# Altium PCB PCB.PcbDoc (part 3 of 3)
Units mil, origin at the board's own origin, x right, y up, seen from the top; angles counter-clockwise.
Board outline 5000 x 3500 mil, 8 copper layers (Top Layer, L2, L3, L4, L5, L6, L7, Bottom Layer), stack 46.9 mil thick; 123 components, 45 nets, 510 pads, 1300 vias.
Unrouted connection lines stored in the file: 12.
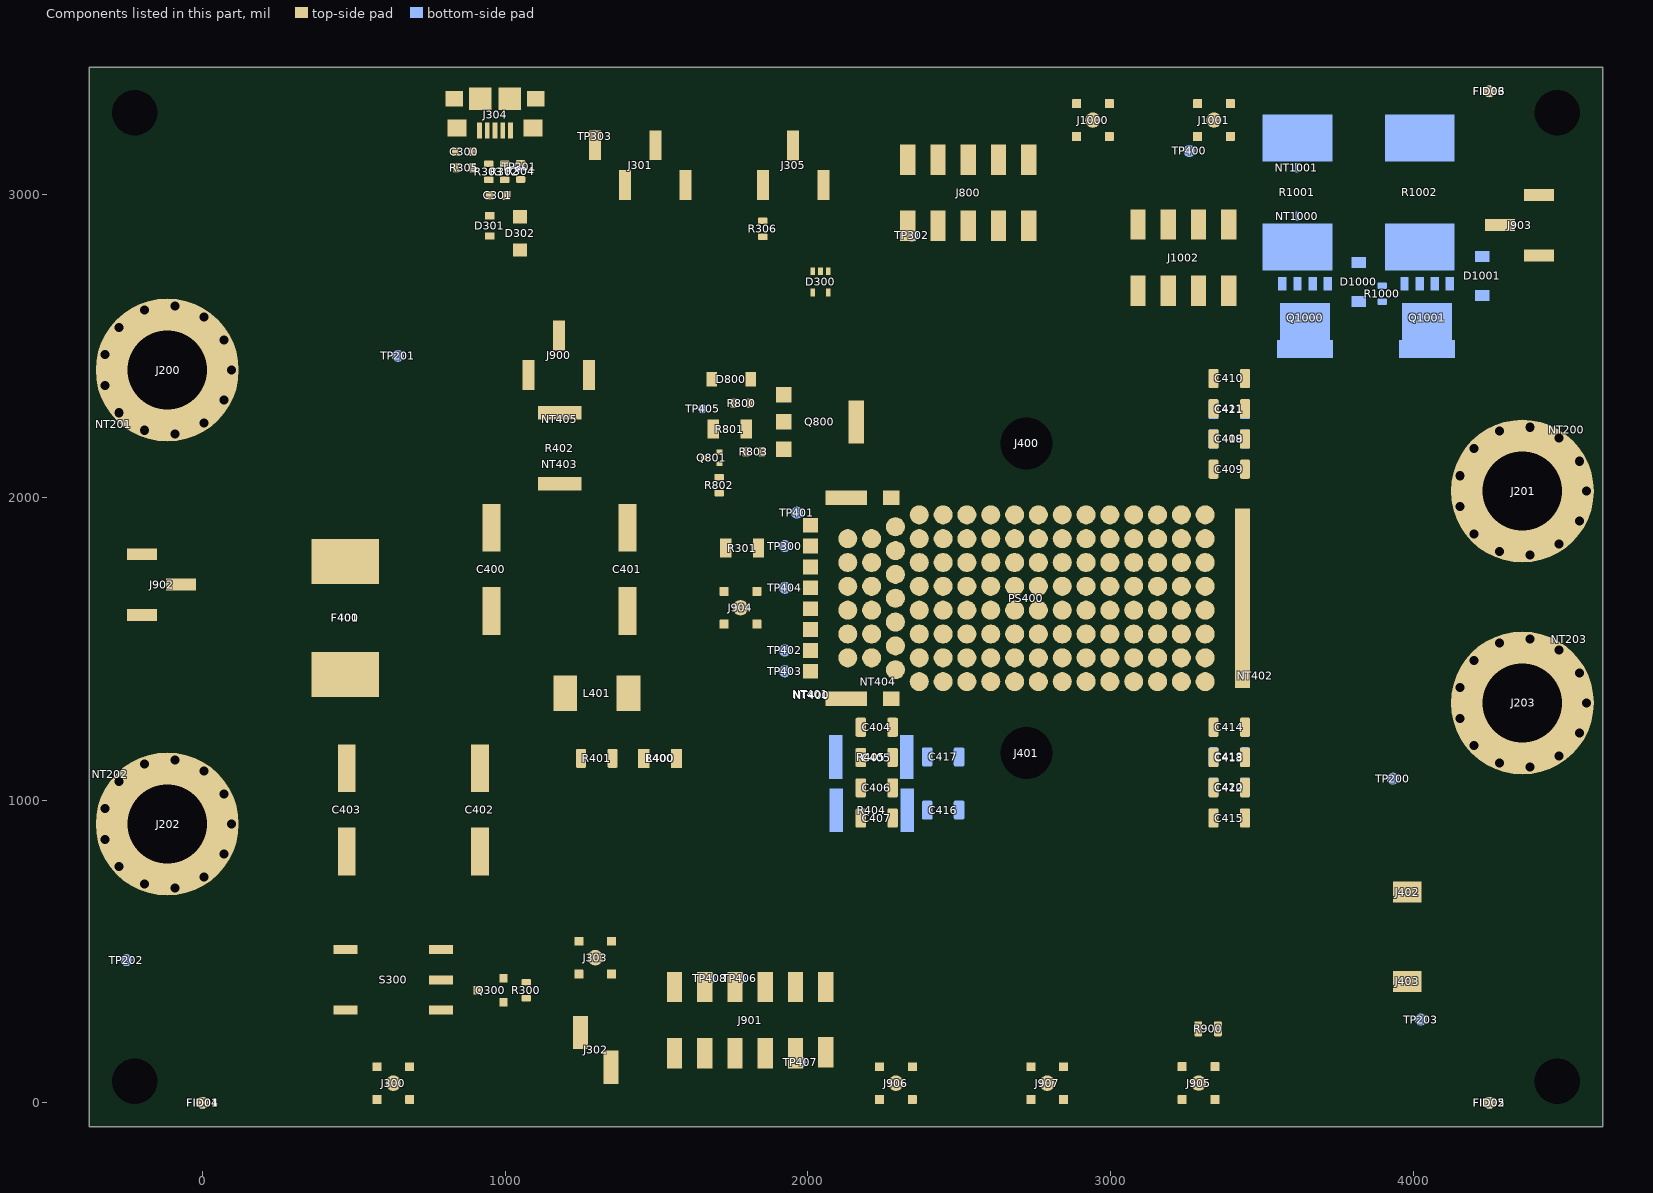
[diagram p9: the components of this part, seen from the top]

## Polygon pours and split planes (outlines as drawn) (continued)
QDISG on Top Layer "Top-No Net" (solid, remove dead copper, pour order 16200): 2492.46,3196 2492.46,3064.42 2668.46,3064.42 2668.46,3196
RDISG on Top Layer "Top-No Net" (solid, remove dead copper, pour order 16177): 2592.46,2950.09 2668.46,2950.09 2668.46,2810.09 2592.46,2810.09
SCL on Top Layer "Top-No Net" (solid, remove dead copper, pour order 16190): 1264.69,3112.32 1328.69,3112.32 1365.71,3149.35 1365.71,3252.32 1226.34,3252.32 1226.34,3150.67
SDA on Top Layer "Top-No Net" (solid, remove dead copper, pour order 16192): 1430.03,3086.36 1363.35,3086.36 1326.5,3049.51 1326.5,2946.36 1465.87,2946.36 1465.87,3050.51
VSS on Top Layer "Top-No Net" (solid, remove dead copper, pour order 16191): 1629.87,3086.51 1563.51,3086.51 1526.34,3049.35 1526.34,2946.51 1665.71,2946.51 1665.71,3050.67
EN_EXT on Top Layer "Top-No Net" (solid, remove dead copper, pour order 16189): 1464.69,3112.32 1528.69,3112.32 1565.71,3149.35 1565.71,3252.32 1426.34,3252.32 1426.34,3150.67
VDDB_EXT on Top Layer "Top-No Net" (solid, remove dead copper, pour order 16188): 1880.12,3085.21 1821.53,3085.21 1781.6,3045.27 1781.6,2945.21 1920.97,2945.21 1920.97,3044.36
VSS on Top Layer "Top-No Net" (solid, remove dead copper, pour order 16185): 2079.96,3085.37 2021.69,3085.37 1981.44,3045.12 1981.44,2945.37 2120.81,2945.37 2120.81,3044.52
VSS on Top Layer "Top-No Net" (solid, remove dead copper, pour order 16194): 1915.38,3111.18 1986.87,3111.18 2020.81,3145.12 2020.81,3251.18 1881.44,3251.18 1881.44,3145.12
RESR_HI on Top Layer "Top-No Net" (solid, remove dead copper, pour order 16180): 1106,2457.3 1047.41,2457.3 1007.47,2417.36 1007.47,2325.89 1146.84,2325.89 1146.84,2416.45
RESR_LO on Top Layer "Top-No Net" (solid, remove dead copper, pour order 16181): 1306.43,2457.46 1247.56,2457.46 1207.32,2417.21 1207.31,2325.89 1346.68,2325.89 1346.68,2417.21
VSS on Top Layer "Top-No Net" (solid, remove dead copper, pour order 16193): 1141.25,2483.27 1212.75,2483.27 1246.68,2517.21 1246.69,2623.27 1107.32,2623.27 1107.32,2517.21
S_P48V_IN on Top Layer "Top-No Net" (solid, remove dead copper, pour order 16187): -148.91,1783.6 -148.91,1842.19 -188.84,1882.13 -288.91,1882.13 -288.91,1742.76 -189.75,1742.76
S_VSS_IN on Top Layer "Top-No Net" (solid, remove dead copper, pour order 16184): -148.75,1583.76 -148.75,1642.03 -189,1682.28 -288.75,1682.28 -288.75,1542.91 -189.6,1542.91
VSS on Top Layer "Top-No Net" (solid, remove dead copper, pour order 16196): -122.94,1748.34 -122.94,1676.85 -89,1642.91 17.06,1642.91 17.06,1782.28 -89,1782.28
EN_EXT on Top Layer "Top-No Net" (solid, remove dead copper, pour order 16183): 1377.84,169.39 1324.55,169.39 1279.31,124.15 1279.31,29.39 1418.68,29.39 1418.69,128.54
EN on Top Layer "Top-No Net" (solid, remove dead copper, pour order 16199): 1220.16,180.61 1273.45,180.61 1318.69,225.85 1318.69,350 1179.32,350 1179.31,221.46
S_VSS_OUT on Top Layer "Top-No Net" (solid, remove dead copper, pour order 16182): 4364.68,2829.1 4364.68,2775.81 4409.93,2730.57 4504.68,2730.57 4504.68,2869.94 4405.53,2869.94
S_P12V2_OUT on Top Layer "Top-No Net" (solid, remove dead copper, pour order 16186): 4364.68,3029.1 4364.68,2970.82 4404.93,2930.57 4504.68,2930.57 4504.68,3069.94 4405.53,3069.94
P12V2 on Top Layer "Top Layer-P12V2" (solid, remove dead copper, pour order 16223): 3452.97,-78.74 4625.98,-78.74 4625.98,850.26 4625.98,2675.39 4260.98,2675.38 4117.57,2818.8 4117.57,3070 3459.39,3070 3459.39,2585.16 3403.1,2528.87 3403.1,2516.9 3402.48,2031.15 3403.39,2030.24 3411.89,2021.75 3411.89,1960.08 3413.63,1960.08 3414.45,1315.41 3403.39,1304.35 3403.39,242.98 3452.97,193.4
VSS on Top Layer "Top-No Net" (solid, remove dead copper, pour order 16216): 4626.74,1614 4029,1614 4029,1029 4626.74,1029
no net on Top Layer "Top-No Net" (solid, remove dead copper, pour order 16175): 4620,1610
VSS on Top Layer "Top-No Net" (solid, pour order 16215): 4200,3096 4200,3400 3217.97,3400 3217.97,3096
VSS on Top Layer "Top-No Net" (solid, pour order 16206): 3056.97,3147.52 3056.97,3347.46 2826.97,3347.46 2826.97,3147.52
VSS on Top Layer "Top-No Net" (solid, remove dead copper, pour order 16201): 1027,2305.25 1027,2227 1327,2227 1327,2305.25
VSS on Top Layer "Top-No Net" (solid, pour order 16205): 1662.3,1735.91 1662.3,1565.31 1691.64,1535.97 1892.3,1535.97 1892.3,1735.91
NetL400_1 on Top Layer "Top Layer-P48V_FILT" (solid, remove dead copper, pour order 16197): 1308.6,1100.4 1319.5,1089.5 1494.48,1089.5 1505.38,1100.4 1505.38,1175.62 1495.5,1185.5 1319.5,1185.5 1308.6,1174.6
VSS on Top Layer "Top Layer-No Net 11" (solid, remove dead copper, pour order 16222): 2247.52,2461.26 2247.52,1974.68 cw(c2197.91,1974.66) 2197.89,1925.04 2072.55,1925.04 ccw(c2072.53,1915.22) 2062.7,1915.2 2062.7,1419.73 ccw(c2072.87,1419.72) 2072.89,1409.55 2198.31,1409.55 cw(c2198.32,1360.35) 2247.52,1360.34 2247.93,1308.76 2241.33,1302.17 2241.33,322.83 3033.84,322.84 3382.08,322.83 3382.08,881.08 3382.08,2461.26
VSS on Top Layer "Top-No Net" (solid, remove dead copper, pour order 16195): 4338.87,2864.51 4338.87,2936.01 4304.93,2969.94 4198.87,2969.94 4198.87,2830.57 4304.93,2830.57
P48V on Top Layer "Top Layer-No Net 8" (solid, remove dead copper, pour order 16221): -374.02,2731 -374.02,1896 3,1896 64,1835 64,1711.26 660,1711.26 660,2655 584,2731
P48V_FILT on Top Layer "Top Layer-P48V_FILT" (solid, remove dead copper, pour order 16219): 1333.76,1416.24 1333.76,1215 1503,1215 1518.12,1199.88 1518.12,776.27 1763.5,776.27 2213.62,776.27 2213.62,1297.73 2194.81,1316.54 2194.81,1360.34 2057.89,1360.34 1956.66,1360.33 1817,1500 1687,1500 1633,1554 1633,1717 1614.09,1735.91 746.58,1735.91 746.58,1519 1231,1519 1308.6,1441.4
NetC400_2 on Top Layer "Top-No Net" (solid, remove dead copper, pour order 16214): 746.58,2068 746.58,1800 1609.96,1800 1609.96,2068
VSS on Top Layer "Top-No Net" (solid, pour order 16211): 1182.35,598.26 1182.35,379.63 1412.35,379.63 1412.35,598.26
VSS on Top Layer "Top-No Net" (solid, pour order 16208): 3406.1,-34.89 3406.1,165.05 3176.1,165.05 3176.1,-34.89
VSS on Top Layer "Top-No Net" (solid, pour order 16210): 515,165 515,-34.94 745,-34.94 745,165
VSS on Top Layer "Top-No Net" (solid, pour order 16207): 2175.98,165 2175.98,-34.94 2405.98,-34.94 2405.98,165
VSS on Top Layer "Top-No Net" (solid, pour order 16209): 2675.98,165 2675.98,-34.94 2905.98,-34.94 2905.98,165
no net on Top Layer "Top-No Net" (solid, remove dead copper, pour order 16174): 457.98,1274.26
VSS on Top Layer "Top Layer-No Net" (solid, remove dead copper, pour order 16212): 3378.58,1311.85 3382.08,1315.35 3382.08,1327.34 3382.08,2019.24 3378.58,2022.74 3333.99,2022.74 3311.49,2045.24 3293.97,2045.24 3292.89,2022.74 3292.89,1311.85 3303.15,1280.36 3334.64,1311.85
VSS on Top Layer "NONET_L01_P-001" (solid, remove dead copper, pour order 16217): 4625.98,1721.26 4025.98,1721.26 4025.98,2321.26 4625.98,2321.26
VSS on Top Layer "VSS_L01_P16220" (solid, remove dead copper, pour order 16220): -377.18,1296.24 220,1296.24 220,1093 363.42,949.58 1236.44,949.58 1236.44,701 397.73,701 242.97,546.24 -377.18,546.24
no net on Top Layer "clm" (solid, remove dead copper, pour order 16176): 4264.86,190
P48V_FUSED on Top Layer "Top Layer-No Net 7" (solid, remove dead copper, pour order 16218): 396,1015 1224,1015 1297,1088 1297,1154 1236.44,1214.56 1236.44,1327.72 1236.44,1448.56 1193.91,1491.09 269.97,1491.09 269.97,1141.03
P+INV on Top Layer "Top Layer-No Net 3" (solid, remove dead copper, pour order 16198): 2194.81,1974.26 2194.81,2022.74 2194.81,2081.26 2013.78,2081.26 2013.78,1974.26
VSS on Top Layer "Top Layer-No Net 9" (solid, remove dead copper, pour order 16213): 3839.98,551.03 3839.98,251.03 4244.98,251.03 4244.98,551.03
USB_SHELL on Top Layer "Top-NetC200_1" (solid, remove dead copper, pour order 16204): 871.63,3179.03 871.63,3273.53 878.13,3280.03 1053.63,3280.03 1060.63,3273.03 1060.63,3179.03 1148.13,3179.03 1148.13,3356.03 787.13,3356.03 787.13,3179.03
VSS on L2 "L2-No Net" (solid, remove dead copper, pour order 16227): -374.02,3421.26 4625.98,3421.26 4625.98,-78.74 -373.62,-78.74
P12V2 on L2 "L2-No Net 2" (solid, remove dead copper, pour order 16226): 3499.98,1419.26 3561.39,1480.67 3561.39,1853.85 3499.95,1915.29 3491.01,1915.29 3471.44,1895.72 3471.44,1438.89 3491.07,1419.26
P+INV on L2 "L2-No Net 1" (solid, remove dead copper, pour order 16224): 2112.44,2081.89 2172.44,2081.89 2190.44,2063.89 2192.44,2061.89 2192.44,2055.89 2192.44,2052.89 2172.44,2032.89 2080.44,2032.89 2061.44,2051.89 2059.44,2053.89 2059.44,2059.89 2059.44,2060.89 2080.44,2081.89 2095.44,2081.89
P48V_FILT on L2 "L2-No Net 1" (solid, remove dead copper, pour order 16225): 2078.58,1300.97 2203.54,1300.98 2203.54,1280.98 2183.91,1280.98 2127.73,1224.8 1979.63,1224.8 1973.11,1231.32 1973.11,1295.38 2020.98,1343.26 2036.3,1343.26
VSS on L4 "L2-No Net" (solid, remove dead copper, pour order 16248): -374.02,3421.26 5106.24,3421.26 5106.24,-159.52 -373.61,-159.52
P12V2 on L4 "L4-P12V2" (solid, remove dead copper, pour order 16245): 4107,2418 4107,2448 4095,2460 4050.01,2460 3903,2607 3823,2607 3782,2607 3635,2460 3591,2460 3579,2448 3579,2418 3586,2411 4100,2411
P12V2 on L4 "L2-No Net 2" (solid, remove dead copper, pour order 16244): 3499.98,1419.26 3561.39,1480.67 3561.39,1853.85 3499.95,1915.29 3491.01,1915.29 3471.44,1895.72 3471.44,1438.89 3491.07,1419.26
P48V_FILT on L4 "L2-No Net 1" (solid, remove dead copper, pour order 16242): 2078.58,1300.97 2203.54,1300.98 2203.54,1280.98 2183.91,1280.98 2127.73,1224.8 1979.63,1224.8 1973.11,1231.32 1973.11,1295.38 2020.98,1343.26 2036.3,1343.26
P48V_FUSED on L4 "Top Layer-No Net 7" (solid, remove dead copper, pour order 16247): 279,1071.31 1296.48,1071.09 1296.48,1465 837,1465 781,1521 279,1521
P48V on L4 "Top-No Net" (solid, remove dead copper, pour order 16246): 280,1945 280,1705 660,1705 660,1945
P48V_FILT on L4 "Top-No Net" (solid, remove dead copper, pour order 16243): 1387.95,1465.2 1381,1458.25 1381,1247.75 1387.54,1241.2 1524.78,1241.2 1531.12,1247.54 1531.12,1458.24 1524.16,1465.2
P+INV on L4 "L2-No Net 1" (solid, remove dead copper, pour order 16241): 2112.44,2081.89 2172.44,2081.89 2190.44,2063.89 2192.44,2061.89 2192.44,2055.89 2192.44,2052.89 2172.44,2032.89 2080.44,2032.89 2061.44,2051.89 2059.44,2053.89 2059.44,2059.89 2059.44,2060.89 2080.44,2081.89 2095.44,2081.89
VSS on L5 "L2-No Net" (solid, remove dead copper, pour order 16257): -374.02,3421.26 4625.99,3421.26 4625.98,-78.74 -373.62,-78.74
P12V2 on L5 "L4-P12V2" (solid, remove dead copper, pour order 16254): 4107,2418 4107,2448 4095,2460 4050.01,2460 3903,2607 3823,2607 3782,2607 3635,2460 3591,2460 3579,2448 3579,2418 3586,2411 4100,2411
P12V2 on L5 "L2-No Net 2" (solid, remove dead copper, pour order 16252): 3499.98,1419.26 3561.39,1480.67 3561.39,1853.85 3499.95,1915.29 3491.01,1915.29 3471.44,1895.72 3471.44,1438.89 3491.07,1419.26
P48V_FILT on L5 "L2-No Net 1" (solid, remove dead copper, pour order 16250): 2078.58,1300.97 2203.54,1300.98 2203.54,1280.98 2183.91,1280.98 2127.73,1224.8 1979.63,1224.8 1973.11,1231.32 1973.11,1295.38 2020.98,1343.26 2036.3,1343.26
P48V_FUSED on L5 "Top Layer-No Net 7" (solid, remove dead copper, pour order 16256): 279,1071.31 1296.48,1071.09 1296.48,1465 837,1465 781,1521 279,1521
P48V on L5 "Top-No Net" (solid, remove dead copper, pour order 16255): 280,1945 280,1705 660,1705 660,1945
P48V_FILT on L5 "Top-No Net" (solid, remove dead copper, pour order 16251): 1387.95,1465.2 1381,1458.25 1381,1247.75 1387.54,1241.2 1524.78,1241.2 1531.12,1247.54 1531.12,1458.24 1524.16,1465.2
P48V on L5 "Top-No Net" (solid, remove dead copper, pour order 16253): 498.44,1298.51 504.98,1291.97 504.98,1064.05 498.44,1057.51 308.44,1057.51 301.44,1064.51 301.44,1292.47 307.49,1298.51
P+INV on L5 "L2-No Net 1" (solid, remove dead copper, pour order 16249): 2112.44,2081.89 2172.44,2081.89 2190.44,2063.89 2192.44,2061.89 2192.44,2055.89 2192.44,2052.89 2172.44,2032.89 2080.44,2032.89 2061.44,2051.89 2059.44,2053.89 2059.44,2059.89 2059.44,2060.89 2080.44,2081.89 2095.44,2081.89
VSS on L7 "L2-No Net" (solid, remove dead copper, pour order 16276): -374.41,3421.26 4625.99,3421.26 4625.98,-78.74 -374.02,-78.74
P12V2 on L7 "L4-P12V2" (solid, remove dead copper, pour order 16273): 4107,2418 4107,2448 4095,2460 4050.01,2460 3903,2607 3823,2607 3782,2607 3635,2460 3591,2460 3579,2448 3579,2418 3586,2411 4100,2411
P12V2 on L7 "L2-No Net 2" (solid, remove dead copper, pour order 16272): 3499.98,1419.26 3561.39,1480.67 3561.39,1853.85 3499.95,1915.29 3491.01,1915.29 3471.44,1895.72 3471.44,1438.89 3491.07,1419.26
P48V_FILT on L7 "L2-No Net 1" (solid, remove dead copper, pour order 16270): 2078.58,1300.97 2203.54,1300.98 2203.54,1280.98 2183.91,1280.98 2127.73,1224.8 1979.63,1224.8 1973.11,1231.32 1973.11,1295.38 2020.98,1343.26 2036.3,1343.26
P48V_FUSED on L7 "Top Layer-No Net 7" (solid, remove dead copper, pour order 16275): 279,1071.31 1296.48,1071.09 1296.48,1465 837,1465 781,1521 279,1521
P48V on L7 "Top-No Net" (solid, remove dead copper, pour order 16274): 280,1945 280,1705 660,1705 660,1945
P48V_FILT on L7 "Top-No Net" (solid, remove dead copper, pour order 16271): 1387.95,1465.2 1381,1458.25 1381,1247.75 1387.54,1241.2 1524.78,1241.2 1531.12,1247.54 1531.12,1458.24 1524.16,1465.2
P+INV on L7 "L2-No Net 1" (solid, remove dead copper, pour order 16269): 2112.44,2081.89 2172.44,2081.89 2190.44,2063.89 2192.44,2061.89 2192.44,2055.89 2192.44,2052.89 2172.44,2032.89 2080.44,2032.89 2061.44,2051.89 2059.44,2053.89 2059.44,2059.89 2059.44,2060.89 2080.44,2081.89 2095.44,2081.89
P12V2 on L3 "L3-No Net" (solid, remove dead copper, pour order 16240): 4625.98,3421.26 4625.98,-328.74 3402.57,-328.74 3402.57,3421.26
S_VSS on L3 "L3-S_VSS" (solid, remove dead copper, pour order 16231): 2071.26,42.26 2086,57 2086,114 2069.74,130.26 1563.98,130.26 1536.73,103 1536.73,69.52 1563.98,42.26
P+INV on L3 "Top-No Net" (solid, remove dead copper, pour order 16232): 2239,2739 2252,2726 2252,2668 2192.44,2608.44 2192.44,2052.89 2172.44,2032.89 2097,2032.89 2097,2327 2097,2649 2174,2726 2187,2739
P48V on L3 "Top Layer-No Net 8" (solid, remove dead copper, pour order 16238): 454.74,2657.26 -374.02,2657.26 -374.02,1711.26 660,1711.26 660,2452
P48V_FILT on L3 "Top Layer-No Net 4" (solid, remove dead copper, pour order 16237): 869.98,1711.26 1626.98,1711.26 1977.98,1360.26 2172.48,1360.26 2217.98,1314.75 2217.98,776.25 1376.99,776.25 1308,845.24 1308,1429.26 1192.49,1544.77 869.98,1544.77
VSS on L3 "Top-No Net" (solid, pour order 16235): 4200,3093.4 4200,3400 3326.97,3400 3326.97,3093.4
VSS on L3 "L3-No Net 2" (solid, remove dead copper, pour order 16239): 3382.98,2460.26 2379.07,2460.26 2245.98,2327.17 2245.98,2021.17 2156.07,1931.26 2090.98,1931.26 2071.98,1912.26 2071.98,1847.17 2071.98,1424.26 2097.49,1398.75 2170.73,1398.75 2215.89,1353.6 2237.98,1331.51 2237.98,-78.74 3382.98,-78.74 3382.98,1306.63
NetL400_1 on L3 "Top Layer-P48V_FILT" (solid, remove dead copper, pour order 16229): 1308.6,1068 1492,1068 1505.38,1081.38 1505.38,1169.62 1489.5,1185.5 1308.6,1185.5
VSS on L3 "Top-No Net" (solid, remove dead copper, pour order 16234): 280,958.96 280,701.7 1122.03,701.7 1122.03,958.96
NetC400_2 on L3 "Top-No Net" (solid, remove dead copper, pour order 16233): 746.58,2060 746.58,1821 1609.96,1821 1609.96,2060
USB_SHELL on L3 "Top-NetC200_1" (solid, pour order 16230): 1148.5,3247.72 1148.5,3355.72 787.5,3355.72 787.5,3247.72
P+INV on L3 "L2-No Net 1" (solid, remove dead copper, pour order 16228): 2153.34,2101 2190.44,2063.89 2192.44,2061.89 2192.44,2055.89 2192.44,2052.89 2172.44,2032.89 2080.44,2032.89 2061.44,2051.89 2059.44,2053.89 2059.44,2059.89 2059.44,2060.89 2099.55,2101
P48V_FUSED on L3 "Top Layer-No Net 7" (solid, remove dead copper, pour order 16236): 280,1068 1297,1068 1297,1426.74 1191.48,1532.26 280,1532.26
P12V2 on L6 "L3-No Net" (solid, remove dead copper, pour order 16268): 4625.98,3421.26 4625.98,-328.74 3396,-328.74 3396,2461 3384.74,2472.26 2802.98,2472.26 2802.98,2837.26 2577.03,3063.22 2577.03,3421.26
P48V_FILT on L6 "Top Layer-No Net 4" (solid, remove dead copper, pour order 16265): 869.98,1711.26 1544.68,1711.26 1895.69,1360.26 2172.48,1360.26 2217.98,1314.75 2217.98,776.25 1376.99,776.25 1308,845.24 1308,1429.26 1192.49,1544.77 869.98,1544.77
P+INV on L6 "Top-No Net" (solid, remove dead copper, pour order 16261): 2380,3191 2380,3105 2260,2985 2260,2727 2240,2707 2187,2707 2170,2724 2170,3070 2300,3200 2371,3200
P48V on L6 "Top Layer-No Net 8" (solid, remove dead copper, pour order 16266): 454.74,2657.26 -374.02,2657.26 -374.02,1711.26 660,1711.26 660,2452
VSS on L6 "Top-No Net" (solid, pour order 16263): 4200,3093.4 4200,3400 3451,3400 3451,3093.4
NetC400_2 on L6 "Top-No Net" (solid, remove dead copper, pour order 16262): 746.58,2063 746.58,1821 1609.96,1821 1609.96,2063
NetL400_1 on L6 "Top Layer-P48V_FILT" (solid, remove dead copper, pour order 16259): 1308.6,1030.94 1490.94,1030.94 1505.38,1045.38 1505.38,1169.62 1489.5,1185.5 1308.6,1185.5
P48V_FUSED on L6 "Top Layer-No Net 7" (solid, remove dead copper, pour order 16264): 280,1030.94 1297,1030.94 1297,1426.74 1194.48,1529.26 280,1529.26
VSS on L6 "L3-No Net 2" (solid, remove dead copper, pour order 16267): 3367.98,2461.26 2303.58,2461.26 2220.15,2377.83 2220.15,2011.42 2149.98,1941.26 2095.98,1941.26 2071.98,1917.26 2071.98,1847.17 2071.98,1423.26 2094,1401.24 2195.89,1401.24 2237.85,1359.28 2237.85,746 2170,678.15 2170,-78.74 3382.42,-78.74 3382.42,2446.83
USB_SHELL on L6 "Top-NetC200_1" (solid, pour order 16260): 1148.48,3217.26 1148.48,3355.26 787.48,3355.26 787.48,3217.26
P+INV on L6 "L2-No Net 1" (solid, remove dead copper, pour order 16258): 2112.44,2081.89 2172.44,2081.89 2190.44,2063.89 2192.44,2061.89 2192.44,2055.89 2192.44,2052.89 2172.44,2032.89 2080.44,2032.89 2061.44,2051.89 2059.44,2053.89 2059.44,2059.89 2059.44,2060.89 2080.44,2081.89 2095.44,2081.89
VSS on Bottom Layer "Bottom Layer-No Net 2" (solid, remove dead copper, pour order 16298): 4625.99,-78.74 4625.98,3421.26 2241.35,3421.26 2241.35,793.54 2147.98,700.18 2147.98,-78.74
VSOURCE2 on Bottom Layer "Top-No Net" (solid, remove dead copper, pour order 16284): 4161.87,2915.52 4161.87,2743.52 4094.41,2743.52 4094.41,2681.97 3954.97,2681.97 3954.97,2744.52 3882.07,2744.52 3882.07,2915.52
VSOURCE1 on Bottom Layer "Top-No Net" (solid, remove dead copper, pour order 16285): 3757.87,2915.52 3757.87,2743.52 3690.41,2743.52 3690.41,2682 3550.97,2682 3550.97,2744.52 3478.07,2744.52 3478.07,2915.52
NetC417_1 on Bottom Layer "Top-No Net" (solid, remove dead copper, pour order 16281): 2303.93,1216.95 2381.48,1216.95 2413.48,1184.95 2413.48,1101.95 2381.48,1069.95 2303.93,1069.95
NetC416_1 on Bottom Layer "Top-No Net" (solid, remove dead copper, pour order 16280): 2305.48,1039.95 2378.48,1039.95 2410.48,1007.95 2410.48,924.95 2378.48,892.95 2305.48,892.95
VSS on Bottom Layer "Bottom Layer-No Net 1" (solid, remove dead copper, pour order 16299): -374.02,-78.74 2325,-78.26 2325,3421.26 -374.02,3421.26
P48V_FILT on Bottom Layer "Top Layer-No Net 4" (solid, remove dead copper, pour order 16296): 869.98,1711.26 1626.98,1711.26 1977.98,1360.26 2172.48,1360.26 2213.74,1319 2213.74,776.25 1376.99,776.25 1308.59,844.65 1308.59,1414.41 1242,1481 869.98,1481
P12V2 on Bottom Layer "Top-No Net" (solid, remove dead copper, pour order 16290): 4626.74,2314 4029,2314 4029,1729 4626.74,1729
VSS on Bottom Layer "Top Layer-No Net 1" (solid, remove dead copper, pour order 16295): 2241.25,1348.42 2241.25,896.81 3382.08,896.81 3382.08,1348.42
P12V2 on Bottom Layer "Top-No Net" (solid, remove dead copper, pour order 16279): 3465.32,1010.78 3435.05,980.52 3403.32,980.52 3403.32,1201.52 3434.94,1201.52 3465.32,1171.14
P12V2 on Bottom Layer "L2-No Net 2" (solid, remove dead copper, pour order 16283): 3499.98,1419.26 3561.39,1480.67 3561.39,1853.85 3499.95,1915.29 3491.01,1915.29 3471.44,1895.72 3471.44,1438.89 3491.07,1419.26
NetL400_1 on Bottom Layer "Top Layer-P48V_FILT" (solid, remove dead copper, pour order 16282): 1308.6,1071.09 1491.09,1071.09 1505.38,1085.38 1505.38,1169.62 1489.5,1185.5 1308.6,1185.5
P12V2 on Bottom Layer "Top-No Net" (solid, remove dead copper, pour order 16288): 3539.59,2645 3727.65,2645 3759.39,2613.26 3927.26,2613.26 3959,2645 4142.39,2645 4142.39,2399 3539.59,2399
NetC400_2 on Bottom Layer "Top-No Net" (solid, remove dead copper, pour order 16289): 869.98,2063 869.98,1821 1490.98,1821 1490.98,2063
P48V_FUSED on Bottom Layer "Top Layer-No Net 7" (solid, remove dead copper, pour order 16293): 279,1071.31 1296.23,1071.09 1296.23,1404.01 1235.24,1465 837,1465 781,1521 279,1521
P48V on Bottom Layer "Top-No Net" (solid, remove dead copper, pour order 16287): 280,1945 280,1705 660,1705 660,1945
P48V on Bottom Layer "NONET_L01_P-001" (solid, remove dead copper, pour order 16292): -382.02,2121.26 217.98,2121.26 217.98,2721.26 -382.02,2721.26
P48V on Bottom Layer "L2-No Net 3" (solid, remove dead copper, pour order 16277): -117.61,1046.27 -81.31,1046.26 -63.11,1028.07 -63.11,924.69 -66.53,921.26 -137.61,921.27 -157.61,941.27 -158.61,942.27 -158.61,948.27 -158.61,1040.27 -152.61,1046.27
P12V2 on Bottom Layer "Top-No Net" (solid, remove dead copper, pour order 16278): 3465.98,2163.52 3435.72,2133.26 3403.98,2133.26 3403.98,2354.26 3435.61,2354.26 3465.98,2323.89
P12V2 on Bottom Layer "NONET_L01_P-001" (solid, remove dead copper, pour order 16291): 4625.98,1021.26 4025.98,1021.26 4025.98,1621.26 4625.98,1621.26
VSS on Bottom Layer "Top Layer-No Net" (solid, remove dead copper, pour order 16297): 2247.52,2007.26 2303.52,2007.26 ccw(c2313.37,2007.26) 2313.37,1997.41 2821.77,1997.41 ccw(c2821.77,2007.26) 2831.62,2007.26 3382.08,2007.26 3382.08,1990.16 3382.08,1327.34 2831.62,1327.34 ccw(c2821.77,1327.34) 2821.77,1337.18 2313.37,1337.18 ccw(c2313.37,1327.34) 2303.52,1327.34 2247.52,1327.34 2165.31,1409.55 2076.7,1409.55 2062.7,1423.54 2062.7,1915.98 2074.98,1928.26 2197.44,1928.26 2247.52,1978.35
P+INV on Bottom Layer "Top Layer-No Net 3" (solid, remove dead copper, pour order 16286): 2194.81,2002.09 2194.81,2022.74 2194.81,2430.14 2059.89,2430.14 2059.89,1974.26 2166.98,1974.26
VSS on Bottom Layer "Top Layer-No Net 1" (solid, remove dead copper, pour order 16294): 2247.52,1986.22 2247.52,2430.14 3382.08,2430.14 3382.08,1986.22

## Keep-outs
Keep-Out Layer:
  the board outline again, w0.5

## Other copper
Top Layer:
  rectangle net VSS: 905.97,3187.01 948.29,3240.16
  pour cut-out: -224.41,3468.5 cw(c-224.41,3271.65) -27.56,3271.65 cw(c-224.41,3271.65) -224.41,3074.8 cw(c-224.41,3271.65) -421.26,3271.65 cw(c-224.41,3271.65)
  pour cut-out: 4476.38,3468.5 cw(c4476.38,3271.65) 4673.23,3271.65 cw(c4476.38,3271.65) 4476.38,3074.8 cw(c4476.38,3271.65) 4279.53,3271.65 cw(c4476.38,3271.65)
  pour cut-out: 4476.38,267.72 cw(c4476.38,70.87) 4673.23,70.87 cw(c4476.38,70.87) 4476.38,-125.98 cw(c4476.38,70.87) 4279.53,70.87 cw(c4476.38,70.87)
  pour cut-out: -224.41,267.72 cw(c-224.41,70.87) -27.56,70.87 cw(c-224.41,70.87) -224.41,-125.98 cw(c-224.41,70.87) -421.26,70.87 cw(c-224.41,70.87)
  pour cut-out: 2722.47,2279.08 cw(c2722.47,2179.08) 2822.47,2179.08 cw(c2722.47,2179.08) 2722.47,2079.08 cw(c2722.47,2179.08) 2622.47,2179.08 cw(c2722.47,2179.08)
  pour cut-out: 2722.44,1255.51 cw(c2722.44,1155.51) 2822.44,1155.51 cw(c2722.44,1155.51) 2722.44,1055.51 cw(c2722.44,1155.51) 2622.44,1155.51 cw(c2722.44,1155.51)
  pour cut-out: 4251.97,50 ccw(c4251.97,0) 4201.97,0 ccw(c4251.97,0) 4251.97,-50 ccw(c4251.97,0) 4301.97,0 ccw(c4251.97,0)
  pour cut-out: 0,50 cw(c0,0) 50,0 cw(c0,0) 0,-50 cw(c0,0) -50,0 cw(c0,0)
  pour cut-out: 4251.97,3392.52 cw(c4251.97,3342.52) 4301.97,3342.52 cw(c4251.97,3342.52) 4251.97,3292.52 cw(c4251.97,3342.52) 4201.97,3342.52 cw(c4251.97,3342.52)
  region: 2767.5,3064.42 2767.5,3196 2691.5,3196 2691.5,3064.42
  region: 2467.5,2950.09 2467.5,2810.09 2391.5,2810.09 2391.5,2950.09
  region: 2467.5,3064.42 2467.5,3196 2398,3196 2398,3064.42
  region: 1796.73,215.67 1796.73,75.67 1720.73,75.67 1720.73,215.67
  region: 1796.73,330 1796.73,470 1720.73,470 1720.73,330
  region: 4626.74,1616.55
  region net VDDB_CLAMPED: 2692.46,2950.09 2692.46,2810.09 2768.46,2810.09 2768.46,2950.09
  region net P+INV: 2292.46,3064.42 2292.46,3196 2368.46,3196 2368.46,3064.42
  region net VSS: 3053.45,2735.35 3053.45,2595.35 3327,2595.35 3327,2735.35
  region net VGATE: 3053.45,2849.68 3053.45,2989.68 3129.45,2989.68 3129.45,2849.68
  region net P12V2: 3153.45,2849.68 3153.45,2989.68 3229.45,2989.68 3229.45,2849.68
  region net I_SENSE_HI: 3253.45,2849.68 3253.45,2989.68 3429.45,2989.68 3429.45,2849.68
  region net I_SENSE_LO: 3353.45,2735.35 3353.45,2595.35 3429.45,2595.35 3429.45,2735.35
  pour cut-out: 3379.48,210.17 3379.48,286.26 3264.48,286.26 3264.48,208.68
  pour cut-out: 3143.73,-67.28 3143.73,196.18 3436.73,196.18 3436.73,-67.28 3177.38,-67.28 3177.38,-37.28 3406.98,-37.28 3406.98,165.05 3176.1,165.05 3176.1,-67.28
  region net S_P12V2: 1696.73,330 1696.73,470 1624.44,470 1624.44,330
  region net S_P48V_FILT: 1592.44,330 1592.44,470 1520.73,470 1520.73,330
  region net EAO: 2096.73,330 2096.73,470 2020.73,470 2020.73,330
  region net FLT*: 1996.73,330 1996.73,470 1920.73,470 1920.73,330
  region net EN: 1896.73,330 1896.73,470 1820.73,470 1820.73,330
  region: 1738.72,2875.79
  text "Layer 1" at 2115.12,-534.29 h30
L2:
  pour cut-out: 2722.47,2279.08 cw(c2722.47,2179.08) 2822.47,2179.08 cw(c2722.47,2179.08) 2722.47,2079.08 cw(c2722.47,2179.08) 2622.47,2179.08 cw(c2722.47,2179.08)
  pour cut-out: 2722.44,1255.51 cw(c2722.44,1155.51) 2822.44,1155.51 cw(c2722.44,1155.51) 2722.44,1055.51 cw(c2722.44,1155.51) 2622.44,1155.51 cw(c2722.44,1155.51)
  pour cut-out: 4476.38,-54.13 ccw(c4476.38,70.87) 4601.38,70.87 ccw(c4476.38,70.87) 4476.38,195.87 ccw(c4476.38,70.87) 4351.38,70.87 ccw(c4476.38,70.87)
  pour cut-out: -224.41,-54.13 ccw(c-224.41,70.87) -99.41,70.87 ccw(c-224.41,70.87) -224.41,195.87 ccw(c-224.41,70.87) -349.41,70.87 ccw(c-224.41,70.87)
  pour cut-out: -224.41,3146.65 ccw(c-224.41,3271.65) -99.41,3271.65 ccw(c-224.41,3271.65) -224.41,3396.65 ccw(c-224.41,3271.65) -349.41,3271.65 ccw(c-224.41,3271.65)
  pour cut-out: 4476.38,3146.65 ccw(c4476.38,3271.65) 4601.38,3271.65 ccw(c4476.38,3271.65) 4476.38,3396.65 ccw(c4476.38,3271.65) 4351.38,3271.65 ccw(c4476.38,3271.65)
  text "Layer 2" at 2115.12,-534.29 h30
L3:
  pour cut-out: 2722.44,1255.51 cw(c2722.44,1155.51) 2822.44,1155.51 cw(c2722.44,1155.51) 2722.44,1055.51 cw(c2722.44,1155.51) 2622.44,1155.51 cw(c2722.44,1155.51)
  pour cut-out: 2722.47,2279.08 cw(c2722.47,2179.08) 2822.47,2179.08 cw(c2722.47,2179.08) 2722.47,2079.08 cw(c2722.47,2179.08) 2622.47,2179.08 cw(c2722.47,2179.08)
  pour cut-out: 4476.38,-54.13 ccw(c4476.38,70.87) 4601.38,70.87 ccw(c4476.38,70.87) 4476.38,195.87 ccw(c4476.38,70.87) 4351.38,70.87 ccw(c4476.38,70.87)
  pour cut-out: 4476.38,3146.65 ccw(c4476.38,3271.65) 4601.38,3271.65 ccw(c4476.38,3271.65) 4476.38,3396.65 ccw(c4476.38,3271.65) 4351.38,3271.65 ccw(c4476.38,3271.65)
  pour cut-out: -224.41,3146.65 ccw(c-224.41,3271.65) -99.41,3271.65 ccw(c-224.41,3271.65) -224.41,3396.65 ccw(c-224.41,3271.65) -349.41,3271.65 ccw(c-224.41,3271.65)
  pour cut-out: -224.41,-54.13 ccw(c-224.41,70.87) -99.41,70.87 ccw(c-224.41,70.87) -224.41,195.87 ccw(c-224.41,70.87) -349.41,70.87 ccw(c-224.41,70.87)
  text "Layer 3" at 2115.12,-534.29 h30
L4:
  pour cut-out: 2722.44,1255.51 cw(c2722.44,1155.51) 2822.44,1155.51 cw(c2722.44,1155.51) 2722.44,1055.51 cw(c2722.44,1155.51) 2622.44,1155.51 cw(c2722.44,1155.51)
  pour cut-out: 2722.47,2279.08 cw(c2722.47,2179.08) 2822.47,2179.08 cw(c2722.47,2179.08) 2722.47,2079.08 cw(c2722.47,2179.08) 2622.47,2179.08 cw(c2722.47,2179.08)
  pour cut-out: 4476.38,-54.13 ccw(c4476.38,70.87) 4601.38,70.87 ccw(c4476.38,70.87) 4476.38,195.87 ccw(c4476.38,70.87) 4351.38,70.87 ccw(c4476.38,70.87)
  pour cut-out: 4476.38,3146.65 ccw(c4476.38,3271.65) 4601.38,3271.65 ccw(c4476.38,3271.65) 4476.38,3396.65 ccw(c4476.38,3271.65) 4351.38,3271.65 ccw(c4476.38,3271.65)
  pour cut-out: -224.41,3146.65 ccw(c-224.41,3271.65) -99.41,3271.65 ccw(c-224.41,3271.65) -224.41,3396.65 ccw(c-224.41,3271.65) -349.41,3271.65 ccw(c-224.41,3271.65)
  pour cut-out: -224.41,-54.13 ccw(c-224.41,70.87) -99.41,70.87 ccw(c-224.41,70.87) -224.41,195.87 ccw(c-224.41,70.87) -349.41,70.87 ccw(c-224.41,70.87)
  pour cut-out: 4476.38,3146.65 ccw(c4476.38,3271.65) 4601.38,3271.65 ccw(c4476.38,3271.65) 4476.38,3396.65 ccw(c4476.38,3271.65) 4351.38,3271.65 ccw(c4476.38,3271.65)
  text "Layer 4" at 2115.12,-534.29 h30
L5:
  pour cut-out: 2722.44,1255.51 cw(c2722.44,1155.51) 2822.44,1155.51 cw(c2722.44,1155.51) 2722.44,1055.51 cw(c2722.44,1155.51) 2622.44,1155.51 cw(c2722.44,1155.51)
  pour cut-out: 2722.47,2279.08 cw(c2722.47,2179.08) 2822.47,2179.08 cw(c2722.47,2179.08) 2722.47,2079.08 cw(c2722.47,2179.08) 2622.47,2179.08 cw(c2722.47,2179.08)
  pour cut-out: 4476.38,-54.13 ccw(c4476.38,70.87) 4601.38,70.87 ccw(c4476.38,70.87) 4476.38,195.87 ccw(c4476.38,70.87) 4351.38,70.87 ccw(c4476.38,70.87)
  pour cut-out: 4476.38,3146.65 ccw(c4476.38,3271.65) 4601.38,3271.65 ccw(c4476.38,3271.65) 4476.38,3396.65 ccw(c4476.38,3271.65) 4351.38,3271.65 ccw(c4476.38,3271.65)
  pour cut-out: -224.41,3146.65 ccw(c-224.41,3271.65) -99.41,3271.65 ccw(c-224.41,3271.65) -224.41,3396.65 ccw(c-224.41,3271.65) -349.41,3271.65 ccw(c-224.41,3271.65)
  pour cut-out: -224.41,-54.13 ccw(c-224.41,70.87) -99.41,70.87 ccw(c-224.41,70.87) -224.41,195.87 ccw(c-224.41,70.87) -349.41,70.87 ccw(c-224.41,70.87)
  text "Layer 5" at 2115.12,-534.29 h30
L6:
  pour cut-out: 2722.44,1255.51 cw(c2722.44,1155.51) 2822.44,1155.51 cw(c2722.44,1155.51) 2722.44,1055.51 cw(c2722.44,1155.51) 2622.44,1155.51 cw(c2722.44,1155.51)
  pour cut-out: 2722.47,2279.08 cw(c2722.47,2179.08) 2822.47,2179.08 cw(c2722.47,2179.08) 2722.47,2079.08 cw(c2722.47,2179.08) 2622.47,2179.08 cw(c2722.47,2179.08)
  pour cut-out: 4476.38,-54.13 ccw(c4476.38,70.87) 4601.38,70.87 ccw(c4476.38,70.87) 4476.38,195.87 ccw(c4476.38,70.87) 4351.38,70.87 ccw(c4476.38,70.87)
  pour cut-out: 4476.38,3146.65 ccw(c4476.38,3271.65) 4601.38,3271.65 ccw(c4476.38,3271.65) 4476.38,3396.65 ccw(c4476.38,3271.65) 4351.38,3271.65 ccw(c4476.38,3271.65)
  pour cut-out: -224.41,3146.65 ccw(c-224.41,3271.65) -99.41,3271.65 ccw(c-224.41,3271.65) -224.41,3396.65 ccw(c-224.41,3271.65) -349.41,3271.65 ccw(c-224.41,3271.65)
  pour cut-out: -224.41,-54.13 ccw(c-224.41,70.87) -99.41,70.87 ccw(c-224.41,70.87) -224.41,195.87 ccw(c-224.41,70.87) -349.41,70.87 ccw(c-224.41,70.87)
  text "Layer 6" at 2115.12,-534.29 h30
L7:
  pour cut-out: 2722.44,1255.51 cw(c2722.44,1155.51) 2822.44,1155.51 cw(c2722.44,1155.51) 2722.44,1055.51 cw(c2722.44,1155.51) 2622.44,1155.51 cw(c2722.44,1155.51)
  pour cut-out: 2722.47,2279.08 cw(c2722.47,2179.08) 2822.47,2179.08 cw(c2722.47,2179.08) 2722.47,2079.08 cw(c2722.47,2179.08) 2622.47,2179.08 cw(c2722.47,2179.08)
  pour cut-out: 4476.38,-54.13 ccw(c4476.38,70.87) 4601.38,70.87 ccw(c4476.38,70.87) 4476.38,195.87 ccw(c4476.38,70.87) 4351.38,70.87 ccw(c4476.38,70.87)
  pour cut-out: 4476.38,3146.65 ccw(c4476.38,3271.65) 4601.38,3271.65 ccw(c4476.38,3271.65) 4476.38,3396.65 ccw(c4476.38,3271.65) 4351.38,3271.65 ccw(c4476.38,3271.65)
  pour cut-out: -224.41,3146.65 ccw(c-224.41,3271.65) -99.41,3271.65 ccw(c-224.41,3271.65) -224.41,3396.65 ccw(c-224.41,3271.65) -349.41,3271.65 ccw(c-224.41,3271.65)
  pour cut-out: -224.41,-54.13 ccw(c-224.41,70.87) -99.41,70.87 ccw(c-224.41,70.87) -224.41,195.87 ccw(c-224.41,70.87) -349.41,70.87 ccw(c-224.41,70.87)
  text "Layer 7" at 2115.12,-534.29 h30
Bottom Layer:
  pour cut-out: -224.41,3468.5 cw(c-224.41,3271.65) -27.56,3271.65 cw(c-224.41,3271.65) -224.41,3074.8 cw(c-224.41,3271.65) -421.26,3271.65 cw(c-224.41,3271.65)
  pour cut-out: 4476.38,3468.5 cw(c4476.38,3271.65) 4673.23,3271.65 cw(c4476.38,3271.65) 4476.38,3074.8 cw(c4476.38,3271.65) 4279.53,3271.65 cw(c4476.38,3271.65)
  pour cut-out: 4476.38,267.72 cw(c4476.38,70.87) 4673.23,70.87 cw(c4476.38,70.87) 4476.38,-125.98 cw(c4476.38,70.87) 4279.53,70.87 cw(c4476.38,70.87)
  pour cut-out: -224.41,267.72 cw(c-224.41,70.87) -27.56,70.87 cw(c-224.41,70.87) -224.41,-125.98 cw(c-224.41,70.87) -421.26,70.87 cw(c-224.41,70.87)
  pour cut-out: 0,50 cw(c0,0) 50,0 cw(c0,0) 0,-50 cw(c0,0) -50,0 cw(c0,0)
  pour cut-out: 4251.97,50 cw(c4251.97,0) 4301.97,0 cw(c4251.97,0) 4251.97,-50 cw(c4251.97,0) 4201.97,0 cw(c4251.97,0)
  pour cut-out: 4251.97,3392.52 cw(c4251.97,3342.52) 4301.97,3342.52 cw(c4251.97,3342.52) 4251.97,3292.52 cw(c4251.97,3342.52) 4201.97,3342.52 cw(c4251.97,3342.52)
  pour cut-out: 4272.98,2772.7 4272.98,2706.06 4264.4,2706.06 4264.4,2746.24
  pour cut-out: 4184.95,2630.24 4162.79,2630.24 4162.79,2616 4151,2616 4151,2643.57 4184.95,2643.57
  text "Layer 8" at 2115.12,-534.29 h30

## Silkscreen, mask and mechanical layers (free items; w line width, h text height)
Top Overlay:
  circle w10: c4040.04,548.67 r393.7
  lines w4.5: 376.63,482.54 ccw(c376.63,466.85) 360.94,466.85 452.8,375 ; 376.81,482.6 452.3,407.11
  lines w4.8: 1126,-54 1472,-54 ; 1126,700 1472,700
  lines w4.92: 452.63,331 452.63,481
  lines w5: 1081,3077 1203,3077 1268,3012 1268,2966 ; 1126,-54 1126,700 ; 1472,-54 1472,700 ; 1560.11,60.67 1560.11,20.67 1660.11,20.67 1660.11,60.67 ; 1860.11,60.67 1860.11,20.67 1960.11,20.67 ; 1960.11,60.67 1960.11,20.67 ; 2060.11,60.67 2060.11,20.67 1960.11,20.67 ; 2794.89,2560 2264.46,2560 2264.46,3396.52 2794.89,3396.52 ; 2794.89,2560.16 2794.89,3396.68 ; 3396,2531 3396,2581 ; -345,2790 -345,3068 679,3068 679,2790 -345,2790 ; 255,-54 255,415.24 255,700 375.67,700 1106,700 1106,-54 255,-54 ; 719,2634.26 1485.98,2634.26 1560.24,2560 2242,2560 2242,3396.52 719,3396.52 719,2634.26 ; 1491.88,-54 1491.88,926 2125.51,926 2125.51,-54 1491.88,-54
  text "EN" at 1534.6,3273.1 h40 r90
  text "SCL" at 1318.72,3271.32 h40 r90
  text "VSS" at 1971,3270 h40 r90
  text "P+INV" at 2349.98,3203 h40 r90
  text "NC" at 2450.42,3203 h40 r90
  text "QDISG" at 2549.98,3203 h40 r90
  text "QDISG" at 2649.98,3203 h40 r90
  text "NC" at 2750.42,3203 h40 r90
  text "I_SENSE_HI" at 3158.98,3095.26 h40
  text "VGATE" at 2848.98,3088.6 h40
  text "S_P12V2_OUT" at 3857.97,2998.4 h40
  text "VSS" at 2157,2968 h40 r90
  text "VDDB_EXT" at 1783,2962 h40 r90
  text "LABEL" at 73.69,2909 h40
  text "VSS" at 4077.97,2888.4 h40
  text "SDA" at 1413.72,2821.32 h40 r90
  text "VSS" at 1613.72,2816.32 h40 r90
  text "S_VSS_OUT" at 3932.97,2768.4 h40
  text "NC" at 2452.42,2736.7 h40 r90
  text "VSS" at 2349.98,2696.72 h40 r90
  text "VSS" at 2549.98,2696.72 h40 r90
  text "DIGITAL" at 1350.98,2689.26 h40
  text "RDISG" at 2649.98,2623.91 h40 r90
  text "VDDB_C" at 2747.98,2577.26 h40 r90
  text "I_SENSE_LO" at 3043,2478 h40
  text "RESR_HI" at 983.16,2264.38 h40 r90
  text "RESR_LO" at 1401.16,2264.38 h40 r90
  text "P12V2" at 3829,1998 h40
  text "P48V" at 75,1990 h40
  text "S_P48V_IN" at -262,1906 h40
  text "VSS" at 32,1660 h40
  text "S_VSS_IN" at -266,1476 h40
  text "S_P48V_ FILT_AC" at 1639,1356 h40
  text "VSS" at 3865,1291 h40
  text "VSS" at 94.98,1248.26 h40
  text "A" at 2280.73,795.95 h200
  text "+" at 3948.11,764.1 h40
  text "ENABLE" at 524.99,630 h40
  text "PN 52841" at 2516.95,618.79 h55
  text "EN" at 1261.48,590.1 h40
  text "EN=CTRL" at 505,570 h40
  text "DCM 3717 EVAL" at 2359.92,520.94 h55
  text "COUT" at 4385,488 h40 r90
  text "S_P48V_FILT" at 1579.64,486.76 h40 r90
  text "S_P12V2" at 1679.64,486.76 h40 r90
  text "NC" at 1779.64,486.76 h40 r90
  text "EN" at 1879.64,486.76 h40 r90
  text "FLT*" at 1979.64,486.76 h40 r90
  text "EAO" at 2079.64,486.76 h40 r90
  text "SINGOLA" at 2531.86,431.78 h55
  text "-" at 3943.11,219.1 h40
  text "P12V2" at 3456.98,209.26 h40
  text "EN = LOW" at 485.01,203.26 h40
  text "EAO" at 2239.98,169 h40
  text "FLT*" at 2719.98,169 h40
  text "P12V2_AC" at 3456.98,34.26 h40
  text "EN_EXT*" at 790,0 h40
  text "NC" at 1781.64,-8.24 h40 r90
  text "S_VSS" at 1516.77,-36 h40
  text "S_VSS" at 1866.77,-36 h40
  text "EN_EXT" at 1121,-46.66 h40
Bottom Overlay:
  lines w5: 300.98,2728.74 800.98,2728.74 800.98,3228.74 300.98,3228.74 300.98,2728.74 ; 301.97,125 301.97,625 801.97,625 801.97,125 301.97,125 ; 2924,2592 2924,3092 3424,3092 3424,2592 2924,2592 ; 3450,125 3950,125 3950,625 3450,625 3450,125
  text "PAD 1" at 604,2966 h40
  text "PAD 2" at 3227.02,2829.26 h40
  text "PAD 4" at 604.98,362.26 h40
  text "PAD 3" at 3753.02,362.26 h40
Top Solder:
  region: -382.78,2125.98 217.61,2125.98 217.61,2716.54 -382.78,2716.54
  region: -382.78,625.98 217.61,625.98 217.61,1216.54 -382.78,1216.54
  region: 4626.73,1725.98 4026.34,1725.98 4026.34,2316.54 4626.73,2316.54
  region: 4626.74,1025.99 4026.35,1025.99 4026.35,1616.55 4626.74,1616.55
  lines w20: -374.02,-78.74 -374.02,3421.26 4625.98,3421.26 4625.98,-78.74 -374.02,-78.74
Bottom Solder:
  region: 4626.74,1725.99 4026.35,1725.99 4026.35,2316.55 4626.74,2316.55
  region: 4626.74,1025.99 4026.35,1025.99 4026.35,1616.55 4626.74,1616.55
  region: -382.77,2125.99 217.62,2125.99 217.62,2716.55 -382.77,2716.55
  region: -382.77,625.99 217.62,625.99 217.62,1216.55 -382.77,1216.55
  lines w20: -374.02,-78.74 4625.98,-78.74 4625.98,3421.26 -374.02,3421.26 -374.02,-78.74
Top DXF:
  circle w0.98: c9389.76,-157.48 r19.68
  circle w0.98: c9389.76,3500 r19.68
  circle w0.98: c-137.8,3500 r19.68
  circle w0.98: c-137.8,-157.48 r19.68
  lines w0.98: -145.67,-157.48 -129.92,-157.48 ; -145.67,3500 -129.92,3500 ; -137.8,-165.35 -137.8,-149.61 ; -137.8,3492.13 -137.8,3507.87 ; 9381.89,-157.48 9397.64,-157.48 ; 9381.89,3500 9397.64,3500 ; 9389.76,-165.35 9389.76,-149.61 ; 9389.76,3492.13 9389.76,3507.87
Board Outline:
  lines w0.5: 4625.98,-78.74 9625.98,-78.74 9625.98,3421.26 4625.98,3421.26 ; 4625.98,-78.74 4625.98,3421.26 ; 4625.98,-78.74 -374.02,-78.74 -374.02,3421.26 4625.98,3421.26 ; 4625.98,-78.74 4625.98,3421.26
  lines w1: -374.02,-78.74 -216.54,-236.22 9468.5,-236.22 9625.98,-78.74 ; -374.02,3421.26 -216.54,3578.74 9468.5,3578.74 9625.98,3421.26
Board Text Target:
  circle w1: c5125.98,3421.26 r50
  circle w1: c5125.98,3421.26 r25
  circle w1: c-874.02,3421.25 r50
  circle w1: c-874.02,3421.25 r25
  circle w1: c-874.02,-78.75 r50
  circle w1: c-874.02,-78.75 r25
  lines w1: -929.02,-78.75 -884.02,-78.75 ; -929.02,3421.25 -884.02,3421.25 ; -879.02,-78.75 -874.02,-78.75 ; -879.02,3421.25 -874.02,3421.25 ; -874.02,-133.75 -874.02,-88.75 ; -874.02,-83.74 -874.02,-78.75 ; -874.02,-73.75 -874.02,-78.75 ; -874.02,-68.75 -874.02,-23.75 ; -874.02,3366.25 -874.02,3411.25 ; -874.02,3416.26 -874.02,3421.25 ; -874.02,3426.25 -874.02,3421.25 ; -874.02,3431.25 -874.02,3476.25 ; -869.02,-78.74 -874.02,-78.74 ; -869.02,3421.26 -874.02,3421.26 ; -864.02,-78.75 -819.02,-78.75 ; -864.02,3421.25 -819.02,3421.25 ; 5070.98,3421.26 5115.98,3421.26 ; 5120.98,3421.25 5125.98,3421.25 ; 5125.98,3366.26 5125.98,3411.26 ; 5125.98,3416.26 5125.98,3421.25 ; 5125.98,3426.25 5125.98,3421.25 ; 5125.98,3431.26 5125.98,3476.26 ; 5130.98,3421.26 5125.98,3421.26 ; 5135.98,3421.26 5180.98,3421.26
  lines w1.97: 1685,-690 2665,-690 ; 1685,-629.69 2025,-629.69 ; 1685,-550 2665,-550 ; 1685,-420 2665,-420 ; 2025,-690 2025,-550 ; 2025,-630 2375,-630 ; 2375,-750 2375,-550 ; 2375,-630.18 2665,-630.18 ; 1685,-750 1685,-350 2665,-350 2665,-750 1685,-750
  lines w3.94: 1132.29,4150.38 1821.27,4150.38 ; 909.85,4040.14 2051.58,4040.14 2051.58,4227.15 909.85,4227.15 909.85,4040.14
  text "VICOR CONFIDENTIAL" at 1140.17,4166.13 h40
  text "THIS DOCUMENT AND THE DATA DISCLOSED HEREIN OR HEREWITH" at 927.57,4111.01 h19
  text "IS NOT TO BE REPRODUCED, USED OR DISCLOSED IN WHOLE OR" at 931.5,4083.45 h19
  text "IN PART TO ANYONE WITHOUT PERMISSION OF VICOR CORPORATION." at 931.5,4055.89 h19
  text "VICOR CORPORATION" at 1965,-400 h30
  text "3717 DCM SINGOLA" at 2000,-475 h30
  text "DES:" at 1694.67,-590 h20
  text "D.LeBLANC" at 1795,-590 h20
  text "DWG NO." at 2045,-590 h20
  text "Data Release:" at 2395,-590 h20
  text "52841" at 2205.01,-610 h30
  text "DR2" at 2504.88,-621.66 h20
  text "SHEET X OF X" at 2045,-670 h20
  text "DATE:" at 2395.14,-670.38 h20
  text "ENG:" at 1694.35,-671.26 h20
  text "N.Rosselli" at 1768.83,-671.56 h20
  text "6/15/22" at 2493.61,-670.79 h20
  text "FILENAME:" at 1694.67,-730 h20
  text ".Pcb_File_Name_No_Path" at 1871.68,-730.12 h20
  text "SCALE:" at 2395,-730 h20
  text "1X" at 2525,-730 h20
